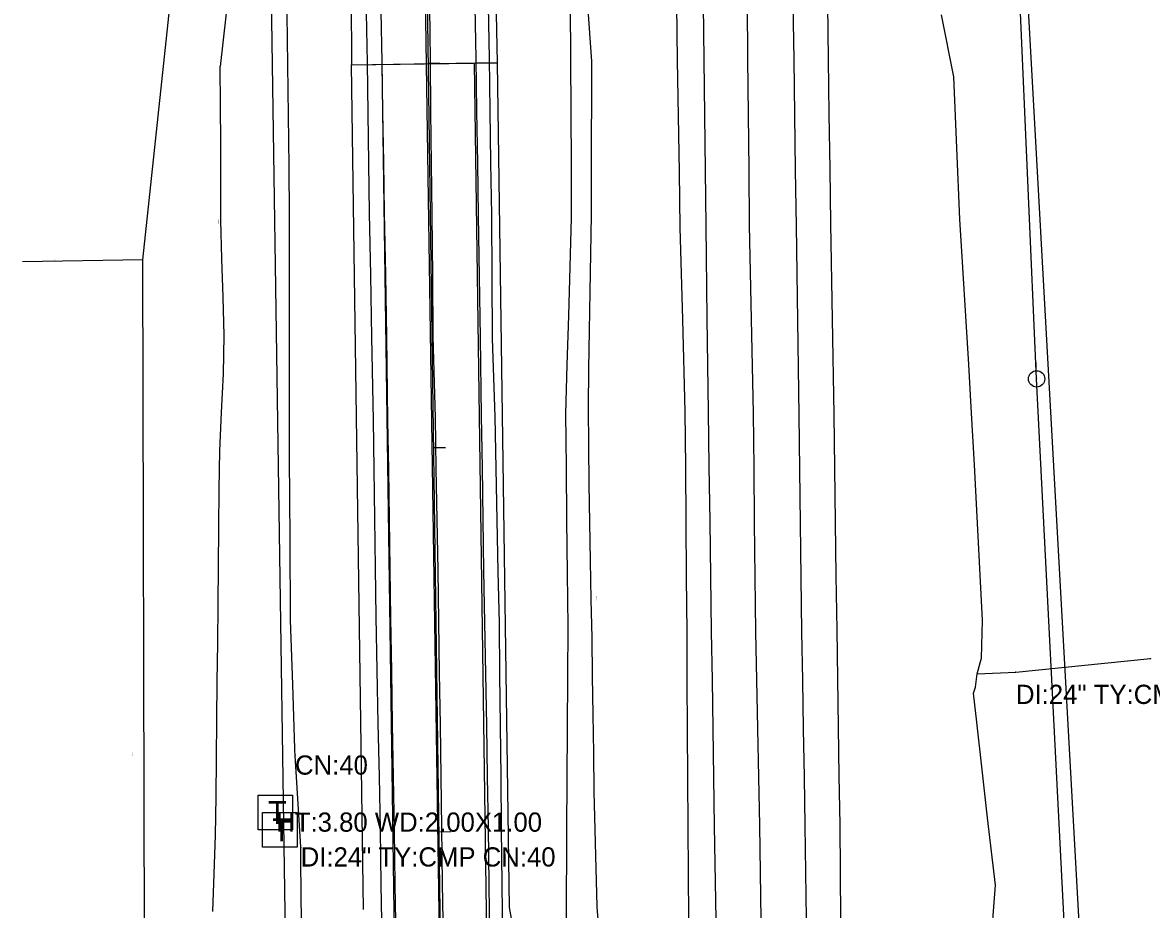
# Model space of a CAD drawing. Extents: x 1674300 to 1677920, y 225056 to 231852.
# Drawn here: x 1677262.1 to 1677555.6, y 229457.6 to 229688.4 of the extents above; entities that cross this region are included whole.
import ezdxf

# ---------------------------------------------------------------- set-up
doc = ezdxf.new("R2010")
doc.units = 0
for name, color, linetype in [('R_Annotation', 7, 'Continuous'), ('R_Axis', 7, 'Continuous'), ('R_Horz Alg', 7, 'Continuous'), ('R_Horz Alg Annot', 7, 'Continuous'), ('R_Proposed Const Limits_Cut', 7, 'Continuous'), ('R_Proposed Const Limits_Fill', 7, 'Continuous'), ('R_Proposed Road_Lane', 7, 'Continuous'), ('R_Proposed Road_Shoulder', 7, 'Continuous'), ('R_ROW', 7, 'Continuous'), ('R_ROW Annot', 7, 'Continuous'), ('S_DITCHLINE', 7, 'Continuous'), ('S_DRG_PT_SYM', 7, 'Continuous'), ('S_EDGE_PAVEMENT', 7, 'Continuous'), ('S_ELECTRIC_UTILITIES', 7, 'Continuous'), ('S_EXIST_ROW', 7, 'Continuous'), ('S_EXISTING_ALIGNMENT', 7, 'Continuous'), ('S_PAVEMENT_CROWN', 7, 'Continuous'), ('S_SHOULDER', 7, 'Continuous'), ('S_SIDE_DRAIN', 7, 'Continuous'), ('S_SIDE_DRAIN_ANNOT', 7, 'Continuous'), ('S_TELEPHONE_UTILITIES', 7, 'Continuous'), ('S_TELEPHONE_UTILITIES_ANNOT', 7, 'Continuous'), ('S_UTILITY_POLE', 7, 'Continuous'), ('S_UTL_PT_SYM', 7, 'Continuous')]:
    doc.layers.add(name, color=color, linetype=linetype)

msp = doc.modelspace()

# ---------------------------------------------------------------- linework, layer by layer
at = {"layer": 'R_Axis'}
for p, q in [((1677346.67, 230027.44), (1677347.61, 229677.42)), ((1677385.61, 229677.95), (1677378.51, 230027.89)), ((1677347.61, 229677.42), (1677385.61, 229677.95)), ((1677347.69, 229677.42), (1677385.61, 229677.96))]:
    msp.add_line(p, q, dxfattribs=at)
at = {"layer": 'R_Horz Alg'}
msp.add_line((1677377.01, 229008.91), (1677360.58, 230177.65), dxfattribs=at)
at = {"layer": 'R_Horz Alg Annot'}
for points in [[(1677370.61, 229677.74), (1677367.61, 229677.7)], [(1677372.02, 229577.75), (1677369.02, 229577.71)], [(1677373.42, 229477.76), (1677370.42, 229477.72)]]:
    msp.add_lwpolyline(points, dxfattribs=at)
at = {"layer": 'R_Proposed Const Limits_Cut'}
for points in [[(1677331.55, 230027.23), (1677331.85, 229955.95), (1677331.75, 229909.6), (1677330.88, 229862.77), (1677328.06, 229806.45), (1677313.48, 229676.94)], [(1677311.55, 229457.04), (1677311.89, 229466.9), (1677312.24, 229476.9), (1677312.4, 229486.91), (1677312.52, 229496.91), (1677312.63, 229506.91), (1677312.72, 229516.91), (1677312.81, 229526.92), (1677312.9, 229536.92), (1677313.02, 229546.92), (1677313.13, 229556.92), (1677313.22, 229566.93), (1677313.34, 229576.93), (1677313.83, 229586.94), (1677314.3, 229596.94), (1677314.5, 229606.95), (1677314.22, 229616.94), (1677313.92, 229626.94), (1677313.6, 229636.94), (1677313.62, 229646.94), (1677313.59, 229656.94), (1677313.52, 229666.94), (1677313.48, 229676.94)]]:
    msp.add_lwpolyline(points, dxfattribs=at)
at = {"layer": 'R_Proposed Const Limits_Fill'}
msp.add_lwpolyline([(1677412.27, 229448.31), (1677411.5, 229458.3), (1677411.49, 229458.45), (1677411.22, 229468.29), (1677410.99, 229478.29), (1677410.76, 229488.29), (1677410.66, 229498.29), (1677410.5, 229508.29), (1677410.31, 229518.29), (1677410.17, 229528.28), (1677409.96, 229538.28), (1677409.76, 229548.28), (1677409.61, 229558.28), (1677409.45, 229568.28), (1677409.3, 229578.28), (1677409.21, 229588.28), (1677409.35, 229598.28), (1677409.49, 229608.28), (1677409.65, 229618.29), (1677409.81, 229628.29), (1677409.99, 229638.29), (1677410, 229648.29), (1677410.04, 229658.3), (1677410.08, 229668.3), (1677410.12, 229678.3), (1677404.47, 229758.23)], dxfattribs=at)
at = {"layer": 'R_Proposed Road_Lane'}
for p, q in [((1677347.61, 229677.42), (1677385.61, 229677.95)), ((1677362.08, 229217.16), (1677355.61, 229677.53)), ((1677386.08, 229217.34), (1677379.61, 229677.87))]:
    msp.add_line(p, q, dxfattribs=at)
at = {"layer": 'R_Proposed Road_Shoulder'}
for p, q in [((1677350.7, 229457.59), (1677347.61, 229677.42)), ((1677388.7, 229458.13), (1677385.61, 229677.95))]:
    msp.add_line(p, q, dxfattribs=at)
msp.add_lwpolyline([(1677395.88, 229196.45), (1677395.26, 229240.2), (1677394.8, 229415.21), (1677394.66, 229425.21), (1677388.7, 229458.13)], dxfattribs=at)
at = {"layer": 'R_ROW'}
for p, q in [((1677293.32, 229626.65), (1677323.6, 229911.16)), ((1677294.58, 229181.63), (1677293.32, 229626.65))]:
    msp.add_line(p, q, dxfattribs=at)
at = {"layer": 'R_ROW Annot'}
msp.add_line((1677293.32, 229626.65), (1677262.08, 229626.13), dxfattribs=at)
at = {"layer": 'S_DITCHLINE'}
for points in [[(1677403.55, 229454.93), (1677403.6, 229478.23), (1677403.68, 229491.49), (1677403.77, 229504.75), (1677403.86, 229518.01), (1677403.95, 229531.26), (1677403.8, 229545.08), (1677403.64, 229558.9), (1677403.48, 229572.71), (1677403.33, 229586.53), (1677403.71, 229599.28), (1677404.09, 229612.04), (1677404.47, 229624.8), (1677404.85, 229637.56), (1677404.78, 229651.36), (1677404.72, 229665.16), (1677404.65, 229678.97), (1677404.58, 229692.77)], [(1677332.94, 229497.27), (1677332.9, 229499.42), (1677332.33, 229516.14), (1677331.76, 229532.85), (1677331.63, 229554.02), (1677331.51, 229575.18), (1677331.5, 229590.35), (1677331.5, 229605.52), (1677331.51, 229621.71), (1677331.52, 229637.89), (1677331.37, 229651.06), (1677331.21, 229664.23), (1677331.06, 229677.4), (1677330.9, 229690.57)], [(1677513.78, 229446.92), (1677515.05, 229463.87), (1677512.97, 229481.43), (1677511.61, 229493.9), (1677510.26, 229506.37), (1677509.37, 229513.91), (1677509.86, 229515.44), (1677510.34, 229518.94), (1677511.09, 229521.77), (1677511.46, 229522.98), (1677511.69, 229532.84), (1677510.98, 229546.32), (1677510.28, 229559.79), (1677509.58, 229573.27), (1677508.88, 229586.74), (1677508.12, 229599.38), (1677507.36, 229612.01), (1677506.6, 229624.64), (1677505.84, 229637.27), (1677505.04, 229655.77), (1677504.24, 229674.27), (1677501.06, 229690.37)], [(1677510.34, 229518.94), (1677520.35, 229519.32)], [(1677339.09, 229147.6), (1677337.05, 229154.23), (1677340.76, 229158.8), (1677340.29, 229166.32), (1677337.9, 229173.01), (1677337.54, 229184.7), (1677337.47, 229206.29), (1677336.46, 229228.55), (1677335.46, 229250.81), (1677335.75, 229270.19), (1677336.05, 229289.58), (1677334.99, 229313.98), (1677333.93, 229338.37), (1677333.99, 229360.23), (1677334.04, 229382.08), (1677334.5, 229402.19), (1677334.96, 229422.29), (1677334.69, 229446.15), (1677334.41, 229470.02), (1677334.41, 229473.73)]]:
    msp.add_lwpolyline(points, dxfattribs=at)
at = {"layer": 'S_DRG_PT_SYM'}
for points in [[(1677555.42, 229522.92), (1677555.42, 229522.97), (1677555.42, 229522.92), (1677555.37, 229522.92), (1677555.42, 229522.92), (1677555.42, 229522.87), (1677555.42, 229522.92), (1677555.47, 229522.92)], [(1677520.36, 229519.36), (1677520.36, 229519.41), (1677520.36, 229519.36), (1677520.31, 229519.36), (1677520.36, 229519.36), (1677520.36, 229519.31), (1677520.36, 229519.36), (1677520.41, 229519.36)], [(1677332.92, 229497.67), (1677332.92, 229497.72), (1677332.92, 229497.67), (1677332.87, 229497.67), (1677332.92, 229497.67), (1677332.92, 229497.62), (1677332.92, 229497.67), (1677332.97, 229497.67)], [(1677334.4, 229473.76), (1677334.4, 229473.81), (1677334.4, 229473.76), (1677334.35, 229473.76), (1677334.4, 229473.76), (1677334.4, 229473.71), (1677334.4, 229473.76), (1677334.45, 229473.76)]]:
    msp.add_lwpolyline(points, dxfattribs=at)
at = {"layer": 'S_EDGE_PAVEMENT'}
for points in [[(1677383.6, 229449.7), (1677383.44, 229464.22), (1677383.27, 229478.73), (1677383.02, 229492.11), (1677382.77, 229505.49), (1677382.53, 229518.87), (1677382.28, 229532.25), (1677382.06, 229545.67), (1677381.85, 229559.1), (1677381.64, 229572.52), (1677381.43, 229585.94), (1677381.14, 229606.46), (1677380.9, 229622.33), (1677380.66, 229638.21), (1677380.45, 229651.8), (1677380.24, 229665.39), (1677380.02, 229678.98), (1677379.81, 229692.57)], [(1677442.45, 229455.05), (1677442.04, 229479.26), (1677441.85, 229491.93), (1677441.66, 229504.6), (1677441.47, 229517.27), (1677441.27, 229529.94), (1677441.07, 229544.26), (1677440.86, 229558.58), (1677440.65, 229572.9), (1677440.45, 229587.22), (1677440.13, 229611.36), (1677439.8, 229635.51), (1677439.64, 229649.9), (1677439.48, 229664.28), (1677439.31, 229678.67), (1677439.15, 229693.05)], [(1677465.93, 229455.12), (1677465.6, 229479.4), (1677465.39, 229492), (1677465.18, 229504.6), (1677464.97, 229517.2), (1677464.76, 229529.8), (1677464.57, 229543.9), (1677464.39, 229558), (1677464.2, 229572.09), (1677464.02, 229586.19), (1677463.66, 229610.86), (1677463.3, 229635.53), (1677463.1, 229649.96), (1677462.89, 229664.39), (1677462.69, 229678.82), (1677462.49, 229693.25)], [(1677359.23, 229449.72), (1677359, 229463.99), (1677358.76, 229478.26), (1677358.53, 229492.04), (1677358.31, 229505.82), (1677358.08, 229519.61), (1677357.86, 229533.39), (1677357.67, 229546.25), (1677357.48, 229559.11), (1677357.29, 229571.97), (1677357.1, 229584.84), (1677356.8, 229606.58), (1677356.5, 229622.72), (1677356.2, 229638.87), (1677355.99, 229651.98), (1677355.78, 229665.09), (1677355.57, 229678.21), (1677355.36, 229691.32)]]:
    msp.add_lwpolyline(points, dxfattribs=at)
at = {"layer": 'S_ELECTRIC_UTILITIES'}
for p, q in [((1677525.77, 229595.69), (1677514.95, 229844)), ((1677537.26, 229370.07), (1677525.77, 229595.69))]:
    msp.add_line(p, q, dxfattribs=at)
at = {"layer": 'S_EXIST_ROW'}
for p, q in [((1677337.07, 229010.49), (1677299.88, 231497.46)), ((1677555.5, 229117.02), (1677521.25, 229735.57))]:
    msp.add_line(p, q, dxfattribs=at)
at = {"layer": 'S_EXISTING_ALIGNMENT'}
msp.add_line((1677375.22, 229134.43), (1677343.44, 231259.98), dxfattribs=at)
at = {"layer": 'S_PAVEMENT_CROWN'}
for points in [[(1677371.51, 229449.83), (1677371.31, 229464.31), (1677371.11, 229478.79), (1677370.91, 229492.23), (1677370.72, 229505.67), (1677370.53, 229519.11), (1677370.33, 229532.55), (1677370.11, 229545.8), (1677369.88, 229559.05), (1677369.65, 229572.31), (1677369.42, 229585.56), (1677368.88, 229606.73), (1677368.73, 229622.48), (1677368.58, 229638.23), (1677368.43, 229651.74), (1677368.27, 229665.24), (1677368.12, 229678.74), (1677367.96, 229692.25)], [(1677454.11, 229454.96), (1677453.84, 229479.45), (1677453.56, 229492.05), (1677453.29, 229504.65), (1677453.02, 229517.26), (1677452.75, 229529.86), (1677452.6, 229544.09), (1677452.44, 229558.31), (1677452.29, 229572.54), (1677452.14, 229586.76), (1677451.64, 229611.2), (1677451.15, 229635.63), (1677451, 229650.06), (1677450.85, 229664.49), (1677450.7, 229678.91), (1677450.55, 229693.34)]]:
    msp.add_lwpolyline(points, dxfattribs=at)
at = {"layer": 'S_SHOULDER'}
for points in [[(1677386.96, 229449.67), (1677386.8, 229464.17), (1677386.64, 229478.67), (1677386.49, 229492.03), (1677386.35, 229505.38), (1677386.2, 229518.74), (1677386.06, 229532.1), (1677385.78, 229545.52), (1677385.5, 229558.94), (1677385.22, 229572.36), (1677384.94, 229585.78), (1677384.31, 229606.18), (1677384.2, 229622.26), (1677384.09, 229638.33), (1677383.88, 229651.92), (1677383.67, 229665.5), (1677383.46, 229679.08), (1677383.25, 229692.66)], [(1677435.32, 229455.13), (1677435.12, 229479.1), (1677435.06, 229491.75), (1677435, 229504.41), (1677434.94, 229517.06), (1677434.87, 229529.71), (1677434.76, 229544.08), (1677434.64, 229558.44), (1677434.53, 229572.8), (1677434.41, 229587.16), (1677433.76, 229611.13), (1677433.1, 229635.09), (1677432.88, 229649.58), (1677432.65, 229664.07), (1677432.43, 229678.56), (1677432.2, 229693.05)], [(1677474.9, 229455.1), (1677474.67, 229479.64), (1677474.47, 229492.32), (1677474.27, 229505.01), (1677474.07, 229517.7), (1677473.87, 229530.38), (1677473.68, 229544.39), (1677473.48, 229558.39), (1677473.29, 229572.39), (1677473.09, 229586.4), (1677472.67, 229611.22), (1677472.24, 229636.04), (1677472.05, 229650.3), (1677471.85, 229664.55), (1677471.66, 229678.81), (1677471.46, 229693.07)], [(1677355.56, 229449.95), (1677355.36, 229464.12), (1677355.16, 229478.29), (1677354.87, 229492.15), (1677354.58, 229506.01), (1677354.29, 229519.86), (1677354, 229533.72), (1677353.83, 229546.52), (1677353.65, 229559.33), (1677353.48, 229572.13), (1677353.3, 229584.93), (1677352.89, 229606.52), (1677352.61, 229622.65), (1677352.33, 229638.78), (1677352.13, 229651.82), (1677351.93, 229664.86), (1677351.74, 229677.91), (1677351.54, 229690.95)]]:
    msp.add_lwpolyline(points, dxfattribs=at)
at = {"layer": 'S_SIDE_DRAIN'}
for p, q in [((1677520.36, 229519.36), (1677555.42, 229522.92)), ((1677334.4, 229473.76), (1677332.92, 229497.67))]:
    msp.add_line(p, q, dxfattribs=at)
at = {"layer": 'S_TELEPHONE_UTILITIES'}
for points in [[(1677323.31, 229478.3), (1677323.31, 229487.3), (1677332.31, 229487.3), (1677332.31, 229478.3)], [(1677324.45, 229473.79), (1677324.45, 229482.79), (1677333.45, 229482.79), (1677333.45, 229473.79)]]:
    msp.add_lwpolyline(points, close=True, dxfattribs=at)
at = {"layer": 'S_UTILITY_POLE'}
msp.add_line((1677525.64, 229597.81), (1677525.64, 229599.92), dxfattribs=at)
msp.add_circle((1677525.77, 229595.67), 2.13, dxfattribs=at)
at = {"layer": 'S_UTL_PT_SYM'}
msp.add_lwpolyline([(1677525.77, 229595.69), (1677525.77, 229595.74), (1677525.77, 229595.69), (1677525.72, 229595.69), (1677525.77, 229595.69), (1677525.77, 229595.64), (1677525.77, 229595.69), (1677525.82, 229595.69)], dxfattribs=at)

# ---------------------------------------------------------------- texts
at = {"layer": 'R_Annotation'}
for s, rotation, p in [('CONST. LIMITS', 90.6576, (1677313.04, 229636.01)), ('CONST. LIMITS', 91.3951, (1677411.37, 229537.94)), ('PROP. R/W', 91.0175, (1677290.63, 229497.5))]:
    msp.add_text(s, height=0.12, rotation=rotation, dxfattribs=at).set_placement(p)
at = {"layer": 'R_ROW Annot'}
for s, p in [('+50', (1677270.59, 229626.67)), ("75'", (1677270.56, 229626.85))]:
    msp.add_text(s, height=0.12, rotation=180.9497, dxfattribs=at).set_placement(p)
at = {"layer": 'S_SIDE_DRAIN_ANNOT'}
for s, p in [('DI:24" TY:CMP CN:10 BOTTOM RUSTED OUT', (1677520.41, 229511.07)), ('CN:40', (1677332.92, 229492.67)), ('DI:24" TY:CMP CN:40', (1677334.4, 229468.76))]:
    msp.add_text(s, height=5, rotation=360, dxfattribs=at).set_placement(p)
at = {"layer": 'S_TELEPHONE_UTILITIES'}
for p in [(1677325.87, 229479.8), (1677327.01, 229475.29)]:
    msp.add_text('T', height=6, rotation=360, dxfattribs=at).set_placement(p)
at = {"layer": 'S_TELEPHONE_UTILITIES_ANNOT'}
msp.add_text('HT:3.80 WD:2.00X1.00', height=5, rotation=360, dxfattribs=at).set_placement((1677328.04, 229477.82))

doc.saveas('drawing.dxf')
